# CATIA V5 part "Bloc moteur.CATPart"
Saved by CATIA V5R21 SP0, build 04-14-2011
Part number: bloc moteur
Material "Aluminium": density 2710 kg/m3, Young's modulus 7e+10 Pa, Poisson ratio 0.346, thermal expansion 2.36e-05 1/K
Bounding box of the stored display mesh (mm): x -34 to 34, y -31.5 to 37.5, z -15.714 to 54
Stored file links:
  C:\Users\Olivier\Desktop\redaction CATIA (local)\CATIA\DONNEES\Exercice assemblage 3 (Pompe de ventilation)\Assemblage ensemble bloc moteur (Product inclus)\Bloc moteur.CATPart
  C:\Program Files\Dassault Systemes\B21\win_b64\startup\materials\French\Catalog.CATMaterial
  C:\Users\Olivier\Desktop\redaction CATIA (local)\CATIA\DONNEES\Exercice assemblage 3 (Pompe de ventilation)\Assemblage ensemble bloc moteur (Product inclus)\CATIA_EnvironmentMap_Satin_512x512.jpg
  C:\Users\Olivier\Desktop\redaction CATIA (local)\pompe à moteur de ventilation refait\Pompe_a_moteur_de_ventilation.CATProduct
  C:\Users\Olivier\Desktop\redaction CATIA (local)\pompe à moteur de ventilation refait\Ecrou a collerette M5.CATPart
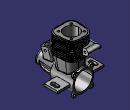
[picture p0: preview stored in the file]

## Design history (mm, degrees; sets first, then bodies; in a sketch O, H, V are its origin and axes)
Body1 (main body), material "Aluminium"
  Sketch1 on yz-plane, origin (0, 0, 0), H (0, 1, 0), V (0, 0, 1)
    line L1 (30, 0) -> (30, -15.5)
    line L2 (30, -15.5) -> (-3.0173, -15.5)
    line L3 (30, 0) -> (-30, 0)
    point P3 (-30, 0)
    line L4 (-30, -9) -> (-6, -11.039)
    point P4 (-30, -9)
    point P5 (-6, -11.039)
    line L5 (-6, -11.039) -> (-3.0173, -15.5)
    line L6 (-30, 0) -> (-30, -9)
    distance P3 P4 = 9
    distance P5 L1 = 36
    length L3 = 60
    length L1 = 15.5
    vertical: L1 V, L6 V
    horizontal: L2 H, L3 H
  Shaft1: profile Sketch1, axis Sketch1.L3, angle 360
  Plane1: type Offset, RefPlane xy-plane, Offset 54
  Sketch2 on Plane1, origin (0, 0, 54), H (1, 0, 0), V (0, 1, 0)
    point P1 (-15.991, -3)
    line L1 (-7.4607, -3) -> (7.4737, -3)
    line L2 (4.6271, 28) -> (-4.6217, 28)
    point P2 (16.009, -3)
    point P3 (14, 28)
    point P4 (-14, 28)
    reference projected line E1 (15.5, 30) -> (-15.5, 30) from edge [face of Shaft1 from Sketch1.L1 | face of Shaft1 from Sketch1.L2]
    line L3 (15.457, 5.5174) -> (14.6061, 18.6467)
    line L4 (-15.4443, 5.5128) -> (-14.6011, 18.6409)
    arc A1 centre (-7.4607, 5) radius 8 from (-7.4607, -3) to (-15.4443, 5.5128) cw
    arc A2 centre (7.4737, 5) radius 8 from (7.4737, -3) to (15.457, 5.5174) ccw
    arc A3 centre (4.6271, 18) radius 10 from (14.6061, 18.6467) to (4.6271, 28) ccw
    arc A4 centre (-4.6217, 18) radius 10 from (-4.6217, 28) to (-14.6011, 18.6409) ccw
    distance E1 L2 = 2
    distance P4 V = 14
    distance P1 P2 = 32
    radius A1 = 8
    radius A2 = 8
    distance P3 P4 = 28
    radius A3 = 10
    radius A4 = 10
    distance L1 L2 = 31
    horizontal: L2 H
    coincidence: L1 P1, L4 P1, L1 P2, L3 P2, L3 P3, L2 P3, L2 P4, L4 P4
    tangency: A1 L1, A1 L4, A2 L1, A2 L3, A3 L3, A3 L2, A4 L2, A4 L4
  Pad1: profile Sketch2, direction (0, 0, -1), length 27
  Sketch3 on end face of Pad1, origin (0, 0, 27), H (1, 0, 0), V (0, -1, 0)
  Sketch4 on end face of Pad1, origin (0, 0, 27), H (1, 0, 0), V (0, -1, 0)
    construction line L1 through (0, 0) direction (1, 0)
    construction line L2 through (0, 0) direction (0, 1)
  Sketch5 on end face of Pad1, origin (0, 0, 27), H (1, 0, 0), V (0, -1, 0)
    reference projected arc E1 centre (-4.6217, -18) radius 10 from (-14.6011, -18.6409) to (-4.6217, -28) ccw from edge [end face of Pad1 | face of Pad1 from Sketch2.A4]
    reference projected arc E2 centre (-7.4607, -5) radius 8 from (-7.4607, 3) to (-15.4443, -5.5128) ccw from edge [end face of Pad1 | face of Pad1 from Sketch2.A1]
    reference projected arc E3 centre (4.6271, -18) radius 10 from (4.6271, -28) to (14.6061, -18.6467) ccw from edge [end face of Pad1 | face of Pad1 from Sketch2.A3]
    line L1 (14.6061, -18.6467) -> (15.457, -5.5174)
    line L2 (7.4737, 3) -> (-7.4607, 3)
    line L3 (-15.4443, -5.5128) -> (-14.6011, -18.6409)
    line L4 (4.6271, -28) -> (-4.6217, -28)
    arc A1 centre (7.4737, -5) radius 8 from (7.4737, 3) to (15.457, -5.5174) cw
    arc A2 centre (4.6271, -18) radius 10 from (14.6061, -18.6467) to (4.6271, -28) cw
    arc A3 centre (-4.6217, -18) radius 10 from (-4.6217, -28) to (-14.6011, -18.6409) cw
    arc A4 centre (-7.4607, -5) radius 8 from (-15.4443, -5.5128) to (-7.4607, 3) cw
    tangency: L1 E3, L2 E2, L3 E1, L4 E1, A1 L1, A2 L4, A3 L3, A4 L2
  Sketch6 on xy-plane, origin (0, 0, 0), H (1, 0, 0), V (0, 1, 0)
    construction line L1 through (0, 0) direction (1, 0)
    construction line L2 through (0, 0) direction (0, 1)
    construction line L3 through (0, 0) direction (1, 0)
    construction line L4 through (0, 0) direction (0, 1)
    point P1 (0, 2.4613)
    construction line L5 through (0, 0) direction (1, 0)
    construction line L6 through (0, 0) direction (0, 1)
    point P2 (-12.8, 0.0613)
    point P3 (12.7992, 0.2685)
    point P4 (11.2, 24.8613)
    point P5 (-11.2, 24.8613)
    line L7 (-5.9184, 0.117) -> (6.0249, 0.2137)
    line L8 (3.7033, 24.8613) -> (-3.6995, 24.8613)
    line L9 (12.3596, 7.0288) -> (11.6864, 17.3804)
    line L10 (-12.3569, 6.9289) -> (-11.6829, 17.3764)
    arc A1 centre (-5.9702, 6.5168) radius 6.4 from (-5.9184, 0.117) to (-12.3569, 6.9289) cw
    arc A2 centre (5.9731, 6.6135) radius 6.4 from (6.0249, 0.2137) to (12.3596, 7.0288) ccw
    arc A3 centre (3.7033, 16.8613) radius 8 from (11.6864, 17.3804) to (3.7033, 24.8613) ccw
    arc A4 centre (-3.6995, 16.8613) radius 8 from (-3.6995, 24.8613) to (-11.6829, 17.3764) ccw
  Loft1: solid, Sections (Sketch5; Sketch6)
  Plane2: type Offset, RefPlane start face of Pad1, Offset 0.5
  Sketch7 on Plane2, origin (0, 0, 53.5), H (1, 0, 0), V (0, -1, 0)
    reference projected curve E1 from start face of Pad1
    construction line L1 through (0, 2.1) direction (1, 0)
    construction line L2 through (0, 2.1) direction (0, 1)
    point P1 (0, 3)
    point P2 (0, 1.25)
    construction line L3 through (0, 1.25) direction (1, 0)
    construction line L4 through (0, 1.25) direction (0, 1)
    point P3 (0, 4.55)
    point P4 (0, -12.5)
    line L5 (8.2211, 4.55) -> (-8.2068, 4.55)
    arc A1 centre (-8.2069, -4.2499) radius 8.7999 from (-8.2068, 4.55) to (-16.9887, -4.814) ccw
    line L6 (-16.9887, -4.814) -> (-16.0612, -19.255)
    arc A2 centre (-5.0839, -18.5501) radius 10.9999 from (-16.0612, -19.255) to (-5.0838, -29.55) ccw
    line L7 (-5.0838, -29.55) -> (5.0898, -29.55)
    arc A3 centre (5.0899, -18.5501) radius 10.9999 from (5.0898, -29.55) to (16.0668, -19.2614) ccw
    line L8 (16.0668, -19.2614) -> (17.0027, -4.8191)
    arc A4 centre (8.2212, -4.2499) radius 8.7999 from (17.0027, -4.8191) to (8.2211, 4.55) ccw
    coincidence: P1 E1, P1 L2
  Pad2: profile Sketch7, direction (0, 0, -1), length 1
  RectPattern1: of Pad2, direction 1 instances 12, spacing 2.2727, along axis of face of Pad1 from Sketch2.A3 reversed
  Sketch8 on start face of Pad1, origin (0, 0, 54), H (1, 0, 0), V (0, 1, 0)
    reference projected line E1 (4.6271, 28) -> (-4.6217, 28) from edge [face of Pad1 from Sketch2.L2 | start face of Pad1]
    point P2 (-4.6217, 28)
    point P3 (-7.4607, -3)
    reference projected line E4 (-14.6011, 18.6409) -> (-15.4443, 5.5128) from edge [face of Pad1 from Sketch2.L4 | start face of Pad1]
    point P7 (-14.6011, 18.6409)
    point P8 (-15.4443, 5.5128)
    circle A1 centre (-9.545, 22.045) radius 1.5
    point P9 (-9.545, 22.045)
    circle A2 centre (-9.545, 2.955) radius 1.5
    point P10 (-9.545, 2.955)
    point P11 (4.6217, 28)
    point P12 (7.4607, -3)
    point P13 (15.4443, 5.5128)
    point P14 (14.6011, 18.6409)
    point P15 (9.545, 22.045)
    circle A3 centre (9.545, 22.045) radius 1.5
    circle A4 centre (9.545, 2.955) radius 1.5
    construction line L1 (14.6011, 18.6409) -> (15.4443, 5.5128)
    circle A5 centre (0, 12.5) radius 10.5
    point P17 (0, 12.5)
    point P18 (0.0027, 28)
    distance P9 P10 = 19.09
    distance P10 V = 9.545
    distance P9 V = 9.545
    distance P15 P17 V = 9.545
    symmetry: P2 P11 V, P3 P12 V, P8 P13 V, P7 P14 V, E4 L1 V, A1 A3 V, A2 A4 V
    coincidence: P17 V
    midpoint: P18 E1
  MultiPocket1: profile Sketch8, domains (length 54; length 8; length 8; length 8; length 8)
  Sketch9 on face of Shaft1 from Sketch1.L1, origin (0, 30, 0), H (-1, 0, 0), V (0, 0, 1)
    circle A1 centre (0, 0) radius 13.25
    circle A2 centre (0, 0) radius 8
  MultiPocket2: profile Sketch9, domains (length 66; length 30)
  Plane3: type Angle, RefPlane face of RectPattern1, Direction edge [face of RectPattern1 | face of RectPattern1], Angle 71
  Sketch10 on Plane3, origin (0.1039, -12.2988, 24.8319), H (-1, -0.0077, -0.0027), V (-0.0082, 0.9455, 0.3256)
    point P1 (0, -8.2811)
    line L1 (7.25, -3.0311) -> (7.25, -13.5311)
    line L2 (5.25, -15.5311) -> (-5.25, -15.5311)
    line L3 (-7.25, -13.5311) -> (-7.25, -3.0311)
    line L4 (-5.25, -1.0311) -> (5.25, -1.0311)
    point P2 (7.25, -15.5311)
    point P3 (-7.25, -15.5311)
    point P4 (-7.25, -1.0311)
    arc A1 centre (-5.25, -3.0311) radius 2 from (-7.25, -3.0311) to (-5.25, -1.0311) cw
    arc A2 centre (5.25, -3.0311) radius 2 from (5.25, -1.0311) to (7.25, -3.0311) cw
    arc A3 centre (5.25, -13.5311) radius 2 from (7.25, -13.5311) to (5.25, -15.5311) cw
    arc A4 centre (-5.25, -13.5311) radius 2 from (-5.25, -15.5311) to (-7.25, -13.5311) cw
    distance P3 P4 = 14.5
    radius A1 = 2
    radius A2 = 2
    distance P2 P3 = 14.5
    radius A3 = 2
    radius A4 = 2
    coincidence: P1 V, L3 P4, L4 P4, L1 P2, L2 P2, L2 P3, L3 P3
    vertical: L1 V, L3 V
    horizontal: L2 H, L4 H
    equidistance: L1 L3 P1, L2 L4 P1
    tangency: A1 L3, A1 L4, A2 L4, A2 L1, A3 L1, A3 L2, A4 L2, A4 L3
  Pad3: profile Sketch10, direction (0, 0.3256, -0.9455), up to the existing solid (limit type 2)
  Sketch11 on start face of Pad3, origin (0.0962, -11.4101, 25.1379), H (1, 0.0077, 0.0027), V (-0.0082, 0.9455, 0.3256)
    circle A1 centre (0, -9.2211) radius 5
    point P1 (0, -9.2211)
    reference projected line E1 (-5.25, -1.9711) -> (5.25, -1.9711) from edge [start face of Pad3 | face of Pad3 from Sketch10.L4]
    distance P1 E1 = 7.25
    coincidence: P1 V
  Pocket1: profile Sketch11, direction (0, 0.3256, -0.9455), through (limit type 6)
  Fillet1: radius 1, on edge [face of Shaft1 from Sketch1.L2 | face of Loft1]; edge [face of Shaft1 from Sketch1.L4 | face of Pad3 from Sketch10.L3]
  Sketch12 on yz-plane, origin (0, 0, 0), H (0, 1, 0), V (0, 0, 1)
    axis line L1 (-14.7367, 0) -> (16.2843, 0)
    point P1 (-14.7367, 0)
    coincidence: P1 H
    horizontal: L1 H
  Plane4: type Angle, RefPlane yz-plane, Direction Sketch12.H, Angle 10
  Sketch13 on Plane4, origin (0, 0, 0), H (0, 1, 0), V (0.1736, 0, 0.9848)
    arc A1 centre (-5.3078, 36.1588) radius 50 from (-3.7677, -13.8175) to (-26.6567, -9.0544) cw
  Stiffener1: ExtendedProfile Sketch13, ThicknessTop 0, ThicknessValue 2
  Plane5: type Angle, RefPlane yz-plane, Direction Sketch12.H, Angle -10
  Sketch14 on Plane5, origin (0, 0, 0), H (0, 1, 0), V (-0.1736, 0, 0.9848)
    arc A1 centre (-5.3078, 36.1588) radius 50 from (-3.7677, -13.8175) to (-26.6567, -9.0544) cw
  Stiffener2: ExtendedProfile Sketch14, ThicknessTop 0, ThicknessValue 2
  CircPattern1: of Stiffener1, Stiffener2, instances 2, angular step 90, axis from face of Shaft1 from Sketch1.L4
  CircPattern2: of Stiffener1, Stiffener2, instances 2, angular step 90, axis from face of Shaft1 from Sketch1.L4
  Sketch15 on yz-plane, origin (0, 0, 0), H (0, 1, 0), V (0, 0, 1)
    construction line L1 (-7.6243, 24.8244) -> (-26.5044, 17.0975)
    point P3 (-12.515, 22.8228)
    coincidence: P3 L1
  Sketch16 on face of Shaft1 from Sketch1.L1, origin (0, 30, 0), H (-1, 0, 0), V (0, 0, 1)
    circle A1 centre (12.7279, 12.7279) radius 1.5
    arc A2 centre (12.7279, 12.7279) radius 3 from (15.2181, 11.0549) to (11.0549, 15.2181) ccw
    line L1 (15.2181, 11.0549) -> (13.5624, 7.5041)
    point P2 (15.2181, 11.0549)
    point P3 (13.5624, 7.5041)
    point P4 (7.5041, 13.5624)
    point P5 (11.0549, 15.2181)
    line L2 (11.0549, 15.2181) -> (7.5041, 13.5624)
    point P7 (-15.2181, 11.0549)
    point P8 (-13.5624, 7.5041)
    point P9 (-7.5041, 13.5624)
    point P10 (-11.0549, 15.2181)
    circle A3 centre (-12.7279, 12.7279) radius 1.5
    arc A4 centre (-12.7279, 12.7279) radius 3 from (-15.2181, 11.0549) to (-11.0549, 15.2181) cw
    line L3 (-15.2181, 11.0549) -> (-13.5624, 7.5041)
    line L4 (-11.0549, 15.2181) -> (-7.5041, 13.5624)
    point P12 (15.2181, -11.0549)
    point P13 (13.5624, -7.5041)
    point P14 (7.5041, -13.5624)
    point P15 (11.0549, -15.2181)
    point P17 (-15.2181, -11.0549)
    point P18 (-13.5624, -7.5041)
    point P19 (-7.5041, -13.5624)
    point P20 (-11.0549, -15.2181)
    circle A5 centre (12.7279, -12.7279) radius 1.5
    arc A6 centre (12.7279, -12.7279) radius 3 from (15.2181, -11.0549) to (11.0549, -15.2181) cw
    line L5 (15.2181, -11.0549) -> (13.5624, -7.5041)
    line L6 (11.0549, -15.2181) -> (7.5041, -13.5624)
    circle A7 centre (-12.7279, -12.7279) radius 1.5
    arc A8 centre (-12.7279, -12.7279) radius 3 from (-15.2181, -11.0549) to (-11.0549, -15.2181) ccw
    line L7 (-15.2181, -11.0549) -> (-13.5624, -7.5041)
    line L8 (-11.0549, -15.2181) -> (-7.5041, -13.5624)
    projected circle E1 centre (0, 0) radius 15.5 from edge [face of Shaft1 from Sketch1.L1 | face of Shaft1 from Sketch1.L2]
    projected arc E2 centre (0, 0) radius 15.5 from (-7.5041, 13.5624) to (-13.5624, 7.5041) ccw from edge [face of Shaft1 from Sketch1.L1 | face of Shaft1 from Sketch1.L2]
    projected arc E3 centre (0, 0) radius 15.5 from (-13.5624, -7.5041) to (-7.5041, -13.5624) ccw from edge [face of Shaft1 from Sketch1.L1 | face of Shaft1 from Sketch1.L2]
    projected arc E4 centre (0, 0) radius 15.5 from (7.5041, -13.5624) to (13.5624, -7.5041) ccw from edge [face of Shaft1 from Sketch1.L1 | face of Shaft1 from Sketch1.L2]
    projected arc E5 centre (0, 0) radius 15.5 from (13.5624, 7.5041) to (7.5041, 13.5624) ccw from edge [face of Shaft1 from Sketch1.L1 | face of Shaft1 from Sketch1.L2]
    radius A2 = 3
    symmetry: P2 P7 V, P3 P8 V, P4 P9 V, P5 P10 V, A1 A3 V, A2 A4 V, L1 L3 V, L2 L4 V, P2 P12 H, P3 P13 H, P4 P14 H, P5 P15 H, P7 P17 H, P8 P18 H, P9 P19 H, P10 P20 H, A1 A5 H, A2 A6 H, L1 L5 H, L2 L6 H, A3 A7 H, A4 A8 H, L3 L7 H, L4 L8 H
  Pad4: profile Sketch16, direction (0, -1, 0), length 2
  Sketch17 on yz-plane, origin (0, 0, 0), H (0, 1, 0), V (0, 0, 1)
    reference projected line E1 through (-11.1809, -3.8499) direction (-0.3256, 0.9455) from axis of face of Pocket1 from Sketch11.A1
    circle A1 centre (-18.5006, 17.4083) radius 1.5
    point P3 (-18.5006, 17.4083)
    reference projected line E2 (-15.1086, 23.8644) -> (-25.0362, 20.446) from edge [start face of Pad3 | face of Pad3 from Sketch10.L3]
    distance P3 E2 = 5
    coincidence: P3 E1
  Pocket2: profile Sketch17, direction (-1, 0, 0), length 9, mirrored extent
  Plane6: type Offset, RefPlane Plane1, Offset 16.5, reversed
  Sketch18 on Plane6, origin (0, 0, 37.5), H (1, 0, 0), V (0, 1, 0)
    projected arc E1 centre (-7.4607, 5) radius 8 from (-15.4443, 5.5128) to (-7.4607, -3) ccw from edge [face of Pad1 from Sketch2.A1 | start face of Pad1]
    point P2 (-7.4607, -3)
    projected line E2 (-7.4607, -3) -> (7.4737, -3) from edge [face of Pad1 from Sketch2.L1 | start face of Pad1]
    projected line E3 (-7.4607, -3) -> (0.0065, -3) from edge [face of Pad1 from Sketch2.L1 | start face of Pad1]
    point P3 (-7.4607, -3)
    projected line E4 (4.6271, 28) -> (-4.6217, 28) from edge [face of Pad1 from Sketch2.L2 | start face of Pad1]
    projected line E5 (0.0027, 28) -> (-4.6217, 28) from edge [face of Pad1 from Sketch2.L2 | start face of Pad1]
    point P6 (-4.6217, 28)
    projected arc E6 centre (-4.6217, 18) radius 10 from (-4.6217, 28) to (-14.6011, 18.6409) ccw from edge [face of Pad1 from Sketch2.A4 | start face of Pad1]
    point P7 (-4.6217, 28)
    projected line E7 (-14.6011, 18.6409) -> (-15.4443, 5.5128) from edge [face of Pad1 from Sketch2.L4 | start face of Pad1]
    line L1 (0.0065, -3) -> (0.0065, -12.5)
    point P11 (0.0065, -3)
    line L2 (0.0065, -12.5) -> (-18.5, -12.5)
    line L3 (-18.5, -12.5) -> (-18.5, 37.5)
    line L4 (-18.5, 37.5) -> (0, 37.5)
    point P15 (0, 37.5)
    line L5 (0, 37.5) -> (0.0027, 28)
    point P16 (0.0027, 28)
    point P17 (0.0046, 12.5)
    distance L2 L4 = 50
    length L4 = 18.5
    midpoint: P11 E2, P16 E4
    vertical: L1 V, L3 V
    horizontal: L2 H, L4 H
    coincidence: P15 V, P2 P3, P6 P7
  Pad5: profile Sketch18, direction (0, 0, 1), length 4.5, mirrored extent
  Sketch19 on face of Pad5 from Sketch18.L5, origin (0.0107, 0, 0), H (-0.0003, 1, 0), V (0, 0, 1)
    circle A1 centre (32.5355, 37.5) radius 1.5
    point P1 (32.5355, 37.5)
    reference projected line E1 (28, 42) -> (37.5, 42) from edge [face of Pad5 from Sketch18.L5 | end face of Pad5]
    reference projected line E2 (37.5, 33) -> (37.5, 42) from edge [face of Pad5 from Sketch18.L4 | face of Pad5 from Sketch18.L5]
    reference projected line E3 (-12.5, 33) -> (-12.5, 42) from edge [face of Pad5 from Sketch18.L1 | face of Pad5 from Sketch18.L2]
    point P2 (37.5, 37.5)
    circle A2 centre (-7.5355, 37.5) radius 1.5
    distance P1 E1 = 4.5
    distance E2 E3 = 50 (reference)
  Pocket3: profile Sketch19, direction (-1, -0.0003, 0), length 8
  Fillet2: radius 4.5, on edge [face of Pad5 from Sketch18.L4 | end face of Pad5]; edge [face of Pad5 from Sketch18.L3 | end face of Pad5]; edge [start face of Pad5 | face of Pad5 from Sketch18.L4]; edge [face of Pad5 from Sketch18.L2 | end face of Pad5]; edge [start face of Pad5 | face of Pad5 from Sketch18.L2]; edge [start face of Pad5 | face of Pad5 from Sketch18.L3]
  Sketch20 on xy-plane, origin (0, 0, 0), H (1, 0, 0), V (0, 1, 0)
    line L1 (13.8085, 26.419) -> (34, 26.419)
    line L2 (34, 26.419) -> (34, 6.419)
    line L3 (34, 6.419) -> (13.7241, 6.419)
    distance L2 V = 34
    length L2 = 20
    horizontal: L1 H, L3 H
    vertical: L2 V
  Stiffener3: ExtendedProfile Sketch20, ThicknessTop 0, ThicknessValue 3.206
  Mirror1: of Stiffener3, about yz-plane
  Sketch21 on face of Stiffener3, origin (0, 0, 1.603), H (1, 0, 0), V (0, 1, 0)
    construction line L1 (28, 19.419) -> (28, 13.419)
    line L2 (31, 19.419) -> (31, 13.419)
    line L3 (25, 13.419) -> (25, 19.419)
    arc A1 centre (28, 13.419) radius 3 from (31, 13.419) to (25, 13.419) cw
    arc A2 centre (28, 19.419) radius 3 from (25, 19.419) to (31, 19.419) cw
    point P3 (31, 19.419)
    point P4 (31, 13.419)
    point P5 (25, 13.419)
    point P6 (25, 19.419)
    point P7 (28, 16.419)
    reference projected line E1 (15.4169, 26.419) -> (34.18, 26.419) from edge [face of Stiffener3 | face of Stiffener3 from Sketch20.L1]
    construction line L4 (-28, 19.419) -> (-28, 13.419)
    point P10 (-31, 19.419)
    point P11 (-31, 13.419)
    point P12 (-25, 13.419)
    point P13 (-25, 19.419)
    point P14 (-28, 16.419)
    line L5 (-31, 19.419) -> (-31, 13.419)
    line L6 (-25, 13.419) -> (-25, 19.419)
    arc A3 centre (-28, 13.419) radius 3 from (-31, 13.419) to (-25, 13.419) ccw
    arc A4 centre (-28, 19.419) radius 3 from (-25, 19.419) to (-31, 19.419) ccw
    distance L1 L2 = 3
    length L1 = 6
    distance P7 E1 = 10
    distance L1 L4 = 56
    vertical: L1 V
    tangency: A1 L2, A2 L2, A1 L3, A2 L3
    midpoint: P7 L1
    symmetry: L1 L4 V, P3 P10 V, P4 P11 V, P5 P12 V, P6 P13 V, P7 P14 V, L2 L5 V, L3 L6 V, A1 A3 V, A2 A4 V
  Pocket4: profile Sketch21, direction (0, 0, -1), length 8
  Plane7: type Offset, RefPlane xy-plane, Offset 54
  Sketch22 on face of Shaft1 from Sketch1.L6, origin (0, -30, 0), H (1, 0, 0), V (0, 0, 1)
    projected circle E1 centre (0, 0) radius 9 from edge [face of Shaft1 from Sketch1.L4 | face of Shaft1 from Sketch1.L6]
    projected circle E2 centre (0, 0) radius 8 from edge [face of Shaft1 from Sketch1.L6 | face of MultiPocket2 from Sketch9.A2]
  Pad6: profile Sketch22, direction (0, -1, 0), length 1.5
